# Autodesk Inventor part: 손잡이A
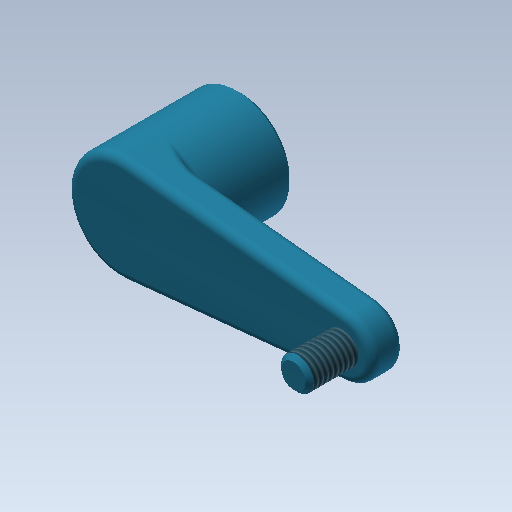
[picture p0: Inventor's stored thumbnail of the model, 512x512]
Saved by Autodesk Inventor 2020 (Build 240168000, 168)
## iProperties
Created: 2022-02
Part Number: 손잡이A
Material: 알루미늄 6061
Document SubType Name: Modeling
Designer: mdu-edu
Density: 2.71 g/cm^3
Mass: 53.5337 g
Surface Area: 72.2064 cm^2
Volume: 19.7541 cm^3
Appearance: 터키옥색
Author: mdu-edu
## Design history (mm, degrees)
sketch "스케치1"
  geometry: C1 r 13 at (0, 0); 1 further point
  constraints: 1 centre point, 1 coincident
  dimensions: "d5" = 13 radius of C1
extrude "돌출1" new body sketch "스케치1" distance "d1" = 22; taper "d2" = 0 deg
sketch "스케치3"
  geometry: L1 (1.3, 12.935)-(55.75, 7.462); L2 (1.3, -12.935)-(55.75, -7.462); C1 r 13 at (0, 0) reference; A1 r 7.5 centre (55, 0) between (55.75, -7.462) and (55.75, 7.462); A2 r 13 centre (0, 0) between (1.3, 12.935) and (1.3, -12.935); 1 further point
  constraints: 4 end point, 4 point on circle, 4 tangent, 2 centre point, 1 coincident, 1 concentric, 1 horizontal alignment
  dimensions: "d15" = 15 diameter of A1; "d16" = 55 distance of point (0, 0) A1.centre
extrude "돌출3" join sketch "스케치3" distance "d17" = 8; taper "d18" = 0 deg
sketch "스케치2"
  geometry: L1 (-7, -7)-(-4.822, -7); L2 (7, -7)-(7, -4.822); L3 (7, 7)-(4.822, 7); L4 (-7, 7)-(-7, 4.822); L5 (-7, -7)-(7, 7); L6 (7, -7)-(-7, 7); L7 (7, 4.822)-(7, 7); L8 (4.822, 7)-(-4.822, 7); L9 (-4.822, 7)-(-7, 7); L10 (-7, 4.822)-(-7, -4.822); L11 (-7, -4.822)-(-7, -7); L12 (-4.822, -7)-(4.822, -7); L13 (4.822, -7)-(7, -7); L14 (7, -4.822)-(7, 4.822); A1 r 8.5 centre (0, 0) between (-4.822, 7) and (-7, 4.822); A2 r 8.5 centre (0, 0) between (4.822, 7) and (-4.822, 7); A3 r 8.5 centre (0, 0) between (7, 4.822) and (4.822, 7); A4 r 8.5 centre (0, 0) between (7, -4.822) and (7, 4.822); A5 r 8.5 centre (0, 0) between (4.822, -7) and (7, -4.822); A6 r 8.5 centre (0, 0) between (-4.822, -7) and (4.822, -7); A7 r 8.5 centre (0, 0) between (-7, -4.822) and (-4.822, -7); A8 r 8.5 centre (0, 0) between (-7, 4.822) and (-7, -4.822); 1 further point
  constraints: 31 point on circle, 28 end point, 18 parallel, 10 perpendicular, 8 centre point, 3 horizontal, 2 midpoint, 1 coincident
  dimensions: "d7" = 14 distance of L2.start L3.start; "d8" = 8.5 radius of A3
extrude "돌출2" cut sketch "스케치2" distance "d9" = 22; taper "d10" = 0 deg
fillet "모깎기1" dims "d30" = 2
fillet "모깎기2" dims "d31" = 2
sketch "스케치4"
  geometry: C1 r 4 at (55, 0); A1 r 7.5 centre (55, 0) between (55.75, -7.462) and (55.75, 7.462) reference; 1 further point
  constraints: 1 centre point, 1 coincident
  dimensions: "d34" = 8 diameter of C1
extrude "돌출4" join sketch "스케치4" distance "d35" = 12; taper "d36" = 0 deg
feature "스레드1" dims "d37" = 10, "d38" = 0
chamfer "모따기1" distance "d12" = 1; stored, may be unused: second distance "d13" = 2, angle "d14" = 45 deg
node "솔리드1"
